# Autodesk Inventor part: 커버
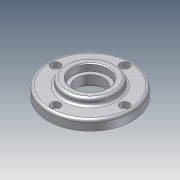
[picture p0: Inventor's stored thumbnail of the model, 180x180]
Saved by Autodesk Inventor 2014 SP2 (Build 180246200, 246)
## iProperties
Company: 한국ATC센터
Created: 2013-01
Part Number: 커버
Document SubType Name: Modeling
Designer: KYOUNG IL JANG
Density: 1 g/cm^3
Material: 일반
Appearance: 기본값
Author: KYOUNG IL JANG
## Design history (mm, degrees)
sketch "스케치1"
  geometry: C1 r 31 at (0, 0) reference; C2 r 50 at (0, 0); 1 further point
  constraints: 1 centre point, 1 coincident
  dimensions: "d41" = 100 diameter of C2
extrude "돌출1" new body sketch "스케치1" distance "d0" = 12; taper "d1" = 0 deg
sketch "스케치2"
  geometry: C1 r 30 at (0, 0); 1 further point
  constraints: 1 centre point, 1 coincident
  dimensions: "d2" = 60 diameter of C1
extrude "돌출2" join sketch "스케치2" distance "d3" = 8; taper "d4" = 0 deg
fillet "모깎기1" dims "d5" = 3
sketch "스케치3" dims "d42" = 82
  geometry: 3 further points
  constraints: 2 vertical alignment, 1 coincident, 2 other
hole "구멍1" sketch "스케치3" at (0, 41) diameter "d6" = 6.6; stored, may be unused: countersink angle "d10" = 90 deg, drill point angle "d12" = 118 deg; dims "d7" = 6, "d8" = 11, "d9" = 6.5, "d11" = 8
hole "구멍2" diameter "d18" = 33; stored, may be unused: countersink angle "d22" = 90 deg, drill point angle "d24" = 118 deg; dims "d16" = 10, "d17" = 10, "d19" = 6, "d20" = 42, "d21" = 8.5, "d23" = 8
sketch "스케치4"
  geometry: C1 r 31 at (0, 0) reference; C2 r 22.5 at (0, 0); 1 further point
  constraints: 1 centre point, 1 coincident
  dimensions: "d43" = 45 diameter of C2
extrude "돌출3" join sketch "스케치4" distance "d25" = 6; taper "d26" = 0 deg
hole "구멍3" diameter "d29" = 50; stored, may be unused: countersink angle "d33" = 90 deg, drill point angle "d35" = 0 deg; dims "d27" = 10, "d28" = 10, "d30" = 6, "d31" = 42, "d32" = 8.5, "d34" = 7
fillet "모깎기2" dims "d36" = 3, "d37" = 0.3
chamfer "모따기1" distance "d38" = 1; stored, may be unused: second distance "d39" = 2, angle "d40" = 45 deg
node "솔리드1"
pattern_circular "원형 패턴1" dims angle "d14" = 360 deg
node "참조9"
node "참조11"
